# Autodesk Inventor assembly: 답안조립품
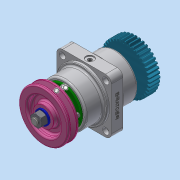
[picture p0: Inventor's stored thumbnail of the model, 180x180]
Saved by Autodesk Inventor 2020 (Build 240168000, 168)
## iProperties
Created: 2023-10
Part Number: 답안조립품
Document SubType Name: Weldment
Designer: CAD14
Weld Material: Welded Aluminum-6061
Author: CAD14
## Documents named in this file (12)
- C:\Users\CAD14\Desktop\731006V1011\답안조립품.iam
- C:\Users\CAD14\Desktop\731006V1011\본체.ipt
- C:\Users\CAD14\Desktop\731006V1011\축.ipt
- C:\Users\CAD14\Desktop\731006V1011\키 5x5.ipt
- C:\Users\CAD14\Desktop\731006V1011\베어링 6204.ipt
- C:\Users\CAD14\Desktop\731006V1011\커버.ipt
- C:\Users\CAD14\Desktop\731006V1011\오일실 20x35x8.ipt
- C:\Users\CAD14\Desktop\731006V1011\V벨트풀리.ipt
- C:\Users\CAD14\Desktop\731006V1011\스퍼기어.ipt
- C:\Users\CAD14\Desktop\731006V1011\볼트 M4x0.7.ipt
- C:\Users\CAD14\Desktop\731006V1011\와셔 12x24.ipt
- C:\Users\CAD14\Desktop\731006V1011\너트 M12x1.25.ipt
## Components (1 placed, 1 different names)
1. V벨트풀리:1
